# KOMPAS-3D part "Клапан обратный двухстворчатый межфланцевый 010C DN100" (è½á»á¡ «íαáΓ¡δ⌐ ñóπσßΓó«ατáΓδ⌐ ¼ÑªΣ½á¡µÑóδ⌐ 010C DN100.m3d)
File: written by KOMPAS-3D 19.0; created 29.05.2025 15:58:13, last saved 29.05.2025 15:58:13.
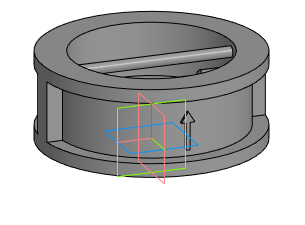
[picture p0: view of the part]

Document properties: Полное имя файла: E:\Dendor Работа Сачек\3D для проекитирвщиков\5.2 Тип 010C, 010C.Y Клапан обратный двухстворчатый межфланцевый\stp_Клапан обратный двухстворчатый межфланцевый 010C\Клапан обратный двухстворчатый межфланцевый 010C DN100.m3d

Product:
- Part/product: Клапан обратный двухстворчатый межфланцевый 010C DN100

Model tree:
1. Операция без истории:1  (labels: Клапан обратный двухстворчатый межфланцевый 010C DN100)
